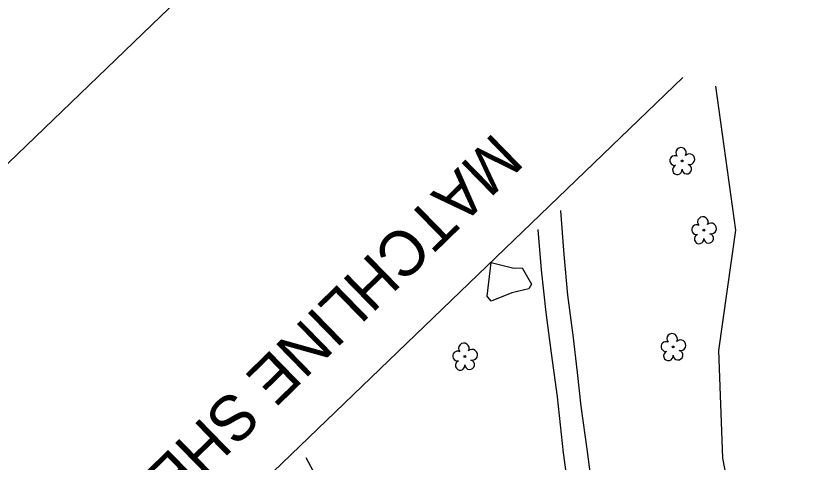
# Model space of a CAD drawing. Extents: x 474972 to 479313, y 498315 to 502691.
# Drawn here: x 475891.1 to 476171.4, y 501725.9 to 501883.5 of the extents above; entities that cross this region are included whole.
import ezdxf

# ---------------------------------------------------------------- set-up
doc = ezdxf.new("R2010")
doc.units = 0
for name, color, linetype in [('CTL Sheet Border CELL', 7, 'Continuous'), ('Exist Roads Soil', 7, 'Continuous'), ('Exist Vegetation Hedge Row', 7, 'Continuous'), ('Exist Vegetation Tree CELL', 7, 'Continuous'), ('Exist Vegetation Woods Line', 7, 'Continuous'), ('Matchline', 7, 'Continuous'), ('Matchline Text', 7, 'Continuous')]:
    doc.layers.add(name, color=color, linetype=linetype)

msp = doc.modelspace()

# ---------------------------------------------------------------- linework, layer by layer
at = {"layer": 'CTL Sheet Border CELL'}
msp.add_lwpolyline([(475037.94, 501013.31), (477341.38, 498619.57), (479016.98, 500231.96), (476713.55, 502625.7)], close=True, dxfattribs=at)
at = {"layer": 'Exist Roads Soil'}
for points in [[(476083.55, 501814.82), (476083.56, 501814.7), (476084.8, 501799.24), (476086.08, 501784.87), (476087.92, 501770.74), (476089.49, 501757.5), (476090.7, 501745.66), (476093, 501729.64), (476094.73, 501716.14), (476097.61, 501700.79), (476101.69, 501683.88)], [(476092.31, 501684.44), (476089.46, 501697.28), (476086.83, 501712.92), (476084.68, 501729.2), (476082.47, 501748.93), (476080.42, 501764.36), (476078.47, 501778.7), (476076.9, 501793.78), (476075.65, 501808.08)]]:
    msp.add_lwpolyline(points, dxfattribs=at)
at = {"layer": 'Exist Vegetation Hedge Row'}
for points in [[(476057.63, 501784.45), (476059.07, 501796.41), (476067.09, 501794.36), (476070.05, 501794.52), (476073.33, 501788.76), (476072.41, 501787.04), (476066.4, 501785.69), (476059.1, 501782.68), (476057.63, 501784.45)], [(475993.54, 501727.54), (476000.81, 501713.95), (476013.85, 501687.14), (476026.43, 501662.24), (476033.03, 501643.73)]]:
    msp.add_lwpolyline(points, dxfattribs=at)
at = {"layer": 'Exist Vegetation Tree CELL'}
for p, q in [((476126.55, 501832.27), (476126.55, 501832.27)), ((476134.26, 501807.83), (476134.26, 501807.83)), ((476123.41, 501766.56), (476123.41, 501766.56)), ((476049.8, 501763.2), (476049.8, 501763.2))]:
    msp.add_line(p, q, dxfattribs=at)
for centre in [(476126.55, 501832.27), (476134.26, 501807.83), (476123.41, 501766.56), (476049.8, 501763.2)]:
    msp.add_circle(centre, 0.326, dxfattribs=at)
for centre, radius, start, end in [((476126.17, 501835.14), 1.86, 330.1651, 219.7134), ((476123.95, 501832.42), 1.73, 62.6636, 279.3457), ((476129.1, 501832.86), 1.9, 257.1011, 134.1999), ((476124.85, 501829.15), 1.69, 111.5671, 6.231), ((476128.22, 501829.37), 1.7, 181.2822, 74.56), ((476133.88, 501810.7), 1.86, 330.1651, 219.7134), ((476131.66, 501807.98), 1.73, 62.6636, 279.3457), ((476136.81, 501808.42), 1.9, 257.1011, 134.1999), ((476132.56, 501804.71), 1.69, 111.5671, 6.231), ((476135.94, 501804.93), 1.7, 181.2822, 74.56), ((476123.03, 501769.44), 1.86, 330.1651, 219.7134), ((476120.81, 501766.72), 1.73, 62.6636, 279.3457), ((476125.96, 501767.15), 1.9, 257.1011, 134.1999), ((476049.41, 501766.07), 1.86, 330.1651, 219.7134), ((476052.35, 501763.78), 1.9, 257.1011, 134.1999), ((476047.19, 501763.35), 1.73, 62.6636, 279.3457), ((476121.71, 501763.44), 1.69, 111.5671, 6.231), ((476125.09, 501763.66), 1.7, 181.2822, 74.56), ((476048.1, 501760.07), 1.69, 111.5671, 6.231), ((476051.47, 501760.3), 1.7, 181.2822, 74.56)]:
    msp.add_arc(centre, radius, start, end, dxfattribs=at)
at = {"layer": 'Exist Vegetation Woods Line'}
for points in [[(476140.99, 501727.29), (476139.47, 501765.27), (476145.59, 501807.86), (476138.42, 501858.69)], [(476187.79, 501751.97), (476187.19, 501730.04), (476202.62, 501717.27), (476190.92, 501678.08), (476166.08, 501679.55), (476149.37, 501683.26), (476140.99, 501727.29)]]:
    msp.add_lwpolyline(points, dxfattribs=at)
at = {"layer": 'Matchline'}
msp.add_line((475766.52, 501515.03), (476126.81, 501861.72), dxfattribs=at)

# ---------------------------------------------------------------- texts
at = {"layer": 'Matchline Text'}
msp.add_text('MATCHLINE SHEET RW02C-6', height=16, rotation=224.2987, dxfattribs=at).set_placement((476060.16, 501842.71))

doc.saveas('drawing.dxf')
